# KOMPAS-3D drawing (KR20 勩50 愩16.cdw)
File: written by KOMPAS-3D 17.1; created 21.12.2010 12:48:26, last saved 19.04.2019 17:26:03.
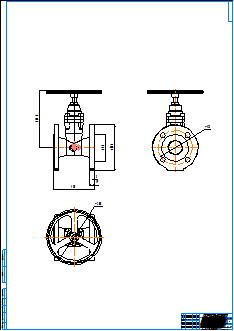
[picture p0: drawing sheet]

Title block, sheet 1: name: KR20 Ду50 Ру16; material: Внимание! Данный продукт является объектом авторского права ООО «Торговый Дом АДЛ». / Запрещается изменение, копирование, распространение / (в том числе путем копирования на другие сайты и ресурсы в Интернете) / или любое иное использование информации и объектов без предварительного / согласия правообладателя (ООО «Торговый Дом АДЛ»).; scale: 1:1; sheets: 1; organisation: ООО "Торговый дом АДЛ"; sheet format: A0; stored path: \\adlc.lan\data\АДЛ_ПКД\3D-модели\ADL production\Клиновые задвижки серии KR ГРАНАР\Клиновые задвижки KR20\KOMPAS 2D\KR20 Ду50 Ру16.cdw

Views: Спереди 1, Проекционный вид 2, Проекционный вид 3, Вид 7, Проекционный вид 8
Dimensions and other numbers on the sheet: 150; 98; 165; 125; 206,5; 3; 19; 200; 1:1; 1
